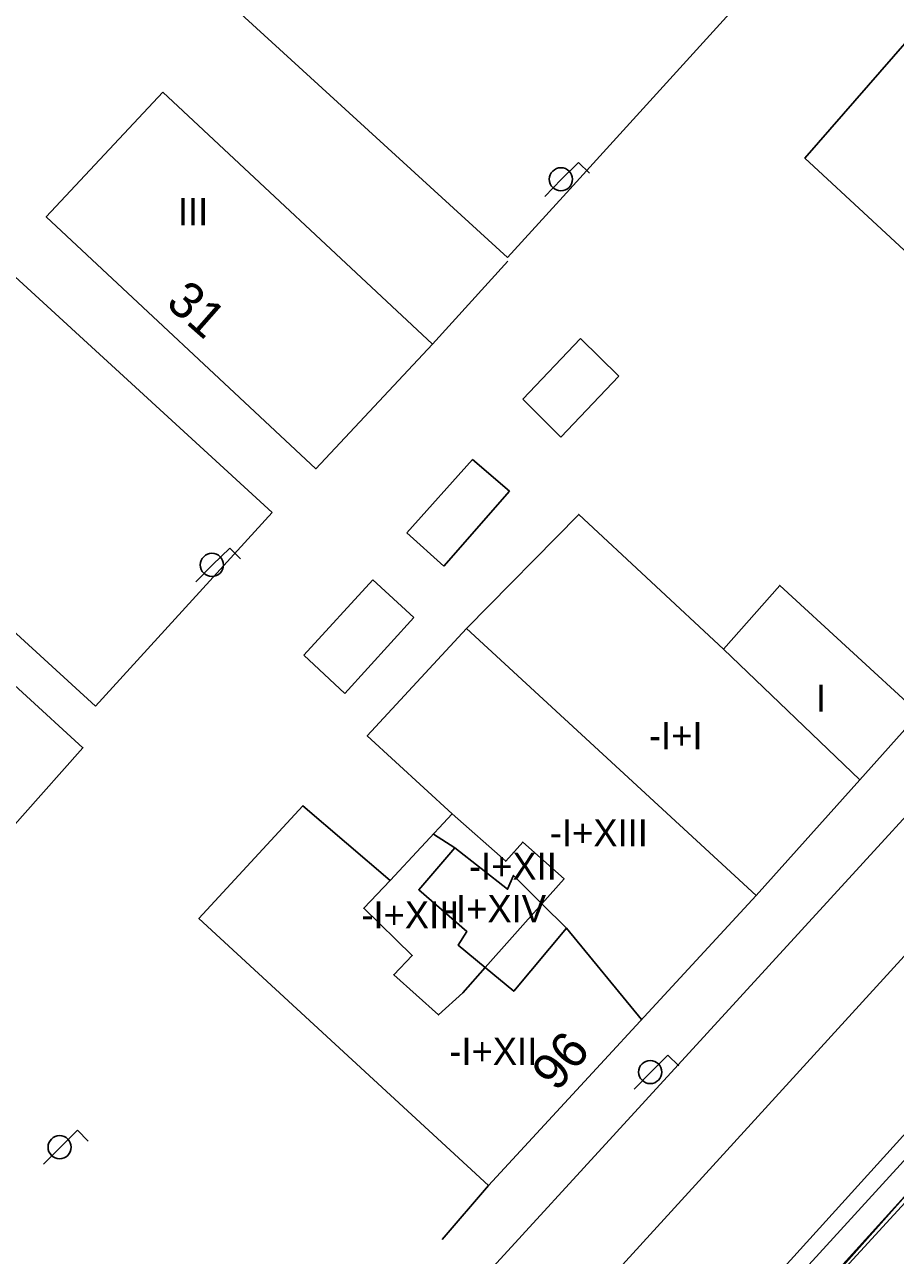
# Model space of a CAD drawing. Extents: x 282771 to 285132, y 4823109 to 4825496.
# Drawn here: x 283891.2 to 283939.2, y 4823179.8 to 4823247.6 of the extents above; entities that cross this region are included whole.
import ezdxf

# ---------------------------------------------------------------- set-up
doc = ezdxf.new("R2010")
doc.units = 0
for name, color, linetype in [('ACERA-BORDILLO', 7, 'Continuous'), ('ACERA-INTERIOR', 7, 'Continuous'), ('BORDILLO', 7, 'Continuous'), ('CARRIL-BICI-AREA', 7, 'Continuous'), ('CARRIL-BICI-EJE', 7, 'Continuous'), ('EDIFICIO', 7, 'Continuous'), ('FAROLA', 7, 'Continuous'), ('MEDIANERA', 7, 'Continuous'), ('NUM-PORTAL', 7, 'Continuous'), ('SENAL-VIARIA', 7, 'Continuous'), ('TXT-ALTURA-EDIFICIO', 7, 'Continuous'), ('ZONA-VERDE', 7, 'Continuous')]:
    doc.layers.add(name, color=color, linetype=linetype)

msp = doc.modelspace()

# ---------------------------------------------------------------- linework, layer by layer
at = {"layer": 'ACERA-BORDILLO'}
msp.add_lwpolyline([(283984.827, 4823248.855), (283984.358, 4823247.176), (283983.789, 4823245.753), (283983.02, 4823244.342), (283981.64, 4823242.802), (283978.955, 4823239.819), (283978.764, 4823239.702), (283978.471, 4823239.716), (283978.134, 4823239.863), (283977.753, 4823240.113), (283975.025, 4823242.49), (283884.411, 4823143.583)], dxfattribs=at)
at = {"layer": 'ACERA-INTERIOR'}
for points in [[(283917.834, 4823234.593), (283913.681, 4823230.032)], [(283914.211, 4823180.673), (283916.771, 4823183.653)]]:
    msp.add_lwpolyline(points, dxfattribs=at)
at = {"layer": 'BORDILLO'}
msp.add_lwpolyline([(283871.998, 4823109), (283916.811, 4823157.903), (283934.68, 4823177.393), (283947.95, 4823192.283), (283978.48, 4823225.343), (283986.08, 4823234.032), (283996.207, 4823245.061)], dxfattribs=at)
at = {"layer": 'CARRIL-BICI-AREA'}
for points in [[(283981.803, 4823255.098), (283978.254, 4823246.945), (283977.963, 4823246.117), (283977.793, 4823245.224), (283977.761, 4823244.294), (283977.875, 4823243.358), (283978.134, 4823242.452), (283978.527, 4823241.607), (283979.031, 4823240.851), (283979.621, 4823240.202), (283980.63, 4823239.243), (283984.45, 4823235.612), (283983.704, 4823234.807), (283976.777, 4823226.889), (283964.668, 4823214.046), (283951.896, 4823199.945), (283946.142, 4823193.592), (283939.611, 4823186.382), (283924.046, 4823169.198), (283904.894, 4823148.356), (283894.675, 4823137.258), (283892.04, 4823134.438), (283884.605, 4823126.478)], [(283874.869, 4823112.031), (283881.491, 4823119.774), (283886.286, 4823124.908), (283893.721, 4823132.868), (283896.361, 4823135.693), (283906.586, 4823146.798), (283925.746, 4823167.648), (283941.315, 4823184.838), (283953.6, 4823198.401), (283966.357, 4823212.485), (283978.48, 4823225.343), (283985.335, 4823233.177), (283987.319, 4823235.517), (283980.962, 4823241.592), (283980.236, 4823242.528), (283979.805, 4823243.694), (283979.752, 4823244.935), (283980.058, 4823246.08), (283983.321, 4823253.576)]]:
    msp.add_lwpolyline(points, dxfattribs=at)
at = {"layer": 'CARRIL-BICI-EJE'}
msp.add_lwpolyline([(284200.857, 4823533.004), (284129.24, 4823405.479), (284127.582, 4823403.82), (284125.509, 4823402.956), (284123.678, 4823402.576), (284122.02, 4823402.195), (284009.854, 4823279.779), (284003.872, 4823269.705), (284003.003, 4823268.955), (284002.056, 4823268.5), (284000.338, 4823268.5), (283996.903, 4823268.5), (283995.66, 4823268.184), (283994.909, 4823267.928), (283994.258, 4823267.355), (283983.558, 4823256.55), (283982.946, 4823255.523), (283978.781, 4823245.646), (283978.781, 4823244.224), (283979.195, 4823242.664), (283979.649, 4823241.636), (283980.36, 4823240.807), (283985.868, 4823235.592), (283870.226, 4823109)], dxfattribs=at)
at = {"layer": 'EDIFICIO'}
for points in [[(283970.34, 4823241.962), (283952.86, 4823223.003), (283934.215, 4823240.276), (283940.48, 4823247.462), (283943.09, 4823244.902), (283944.92, 4823246.872), (283949.71, 4823242.462), (283953.63, 4823246.812), (283948.94, 4823251.172), (283954.3, 4823256.922), (283970.34, 4823241.962)], [(283898.821, 4823243.922), (283913.681, 4823230.032), (283907.261, 4823223.163), (283892.391, 4823237.052), (283898.821, 4823243.922)], [(283867.771, 4823188.923), (283864.572, 4823191.991), (283878.091, 4823206.993), (283856.501, 4823226.332), (283828.232, 4823194.913), (283858.021, 4823167.753), (283850.051, 4823159.423), (283829.922, 4823177.833), (283812.052, 4823194.193), (283856.441, 4823242.592), (283891.081, 4823210.833), (283894.411, 4823207.783), (283891.081, 4823204.023), (283881.621, 4823193.333), (283880.771, 4823194.103), (283873.241, 4823185.723), (283870.611, 4823188.113), (283866.461, 4823183.193), (283864.501, 4823185.023), (283867.771, 4823188.923)], [(283915.561, 4823214.363), (283921.751, 4823220.643), (283929.72, 4823213.223), (283932.83, 4823216.733), (283940.51, 4823209.673), (283937.24, 4823206.023), (283931.52, 4823199.633), (283916.771, 4823183.653), (283900.811, 4823198.373), (283906.541, 4823204.583), (283911.351, 4823200.463), (283914.771, 4823204.133), (283910.091, 4823208.433), (283915.561, 4823214.363)]]:
    msp.add_lwpolyline(points, dxfattribs=at)
at = {"layer": 'FAROLA'}
for p, q in [((283921.741, 4823240.043), (283920.801, 4823239.113)), ((283922.331, 4823239.453), (283921.741, 4823240.043)), ((283920.801, 4823239.113), (283919.871, 4823238.173)), ((283902.504, 4823218.791), (283901.564, 4823217.861)), ((283903.094, 4823218.201), (283902.504, 4823218.791)), ((283901.564, 4823217.861), (283900.634, 4823216.921)), ((283926.665, 4823190.837), (283925.725, 4823189.907)), ((283927.255, 4823190.247), (283926.665, 4823190.837)), ((283925.725, 4823189.907), (283924.795, 4823188.967)), ((283894.11, 4823186.696), (283893.17, 4823185.766)), ((283894.7, 4823186.106), (283894.11, 4823186.696)), ((283893.17, 4823185.766), (283892.24, 4823184.826))]:
    msp.add_line(p, q, dxfattribs=at)
for centre, radius in [((283920.761, 4823239.113), 0.638), ((283901.524, 4823217.861), 0.638), ((283925.685, 4823189.907), 0.637), ((283893.13, 4823185.766), 0.637)]:
    msp.add_circle(centre, radius, dxfattribs=at)
at = {"layer": 'MEDIANERA'}
for points in [[(283931.52, 4823199.633), (283915.561, 4823214.363)], [(283929.72, 4823213.223), (283937.24, 4823206.023)], [(283914.771, 4823204.133), (283917.721, 4823201.523), (283918.661, 4823202.583), (283920.941, 4823200.553), (283919.711, 4823199.173)], [(283914.911, 4823202.273), (283913.741, 4823203.023)], [(283916.581, 4823195.663), (283915.091, 4823196.903), (283915.571, 4823197.663), (283912.931, 4823199.953), (283914.911, 4823202.273)], [(283914.911, 4823202.273), (283917.821, 4823199.983), (283918.141, 4823200.743), (283919.711, 4823199.173)], [(283916.581, 4823195.663), (283915.361, 4823194.283), (283914.011, 4823193.053), (283911.551, 4823195.273), (283912.571, 4823196.323), (283909.891, 4823198.933), (283911.351, 4823200.463)], [(283916.581, 4823195.663), (283919.711, 4823199.173)], [(283919.711, 4823199.173), (283921.071, 4823197.833)], [(283921.071, 4823197.833), (283918.161, 4823194.363), (283916.581, 4823195.663)], [(283921.071, 4823197.833), (283925.211, 4823192.813)]]:
    msp.add_lwpolyline(points, dxfattribs=at)
at = {"layer": 'SENAL-VIARIA'}
msp.add_lwpolyline([(283978.664, 4823238.991), (283889.016, 4823140.787)], dxfattribs=at)
at = {"layer": 'ZONA-VERDE'}
for p, q in [((283858.346, 4823243.676), (283895.108, 4823210.08)), ((283987.197, 4823234.555), (283875.004, 4823112.034)), ((283918.67, 4823226.99), (283921.838, 4823230.336)), ((283921.838, 4823230.336), (283923.965, 4823228.267)), ((283923.965, 4823228.267), (283920.753, 4823224.892)), ((283920.753, 4823224.892), (283918.67, 4823226.99)), ((283912.265, 4823219.632), (283915.887, 4823223.667)), ((283915.887, 4823223.667), (283917.926, 4823221.921)), ((283917.926, 4823221.921), (283914.303, 4823217.783)), ((283895.108, 4823210.08), (283904.852, 4823220.741)), ((283914.303, 4823217.783), (283912.265, 4823219.632)), ((283906.588, 4823212.892), (283910.402, 4823217.046)), ((283910.402, 4823217.046), (283912.656, 4823214.963)), ((283912.656, 4823214.963), (283908.851, 4823210.771)), ((283908.851, 4823210.771), (283906.588, 4823212.892))]:
    msp.add_line(p, q, dxfattribs=at)
for points in [[(283917.824, 4823234.805), (283920.88, 4823238.162), (283939.092, 4823258.202)], [(283904.852, 4823220.741), (283887.11, 4823236.992), (283886.555, 4823236.393), (283884.57, 4823238.147), (283885.143, 4823238.765), (283874.083, 4823248.846), (283873.512, 4823248.231), (283871.222, 4823250.279), (283871.824, 4823250.94), (283868.09, 4823254.338)], [(283905.443, 4823252.47), (283902.279, 4823249.029), (283917.824, 4823234.805)]]:
    msp.add_lwpolyline(points, dxfattribs=at)

# ---------------------------------------------------------------- texts
at = {"layer": 'NUM-PORTAL'}
for s, rotation, p in [('31', 318.62148, (283898.915, 4823232.19)), ('96', 50.17004, (283920.541, 4823188.765))]:
    msp.add_text(s, height=2, rotation=rotation, dxfattribs=at).set_placement(p)
at = {"layer": 'TXT-ALTURA-EDIFICIO'}
for s, p in [('III', (283899.649, 4823236.582)), ('I', (283934.829, 4823209.763)), ('-I+I', (283925.617, 4823207.703)), ('-I+XIII', (283920.152, 4823202.343)), ('-I+XII', (283915.692, 4823200.503)), ('-I+XIV', (283914.314, 4823198.163)), ('-I+XIII', (283909.762, 4823197.823)), ('-I+XII', (283914.612, 4823190.303))]:
    msp.add_text(s, height=1.5, rotation=0.00004, dxfattribs=at).set_placement(p)

doc.saveas('drawing.dxf')
